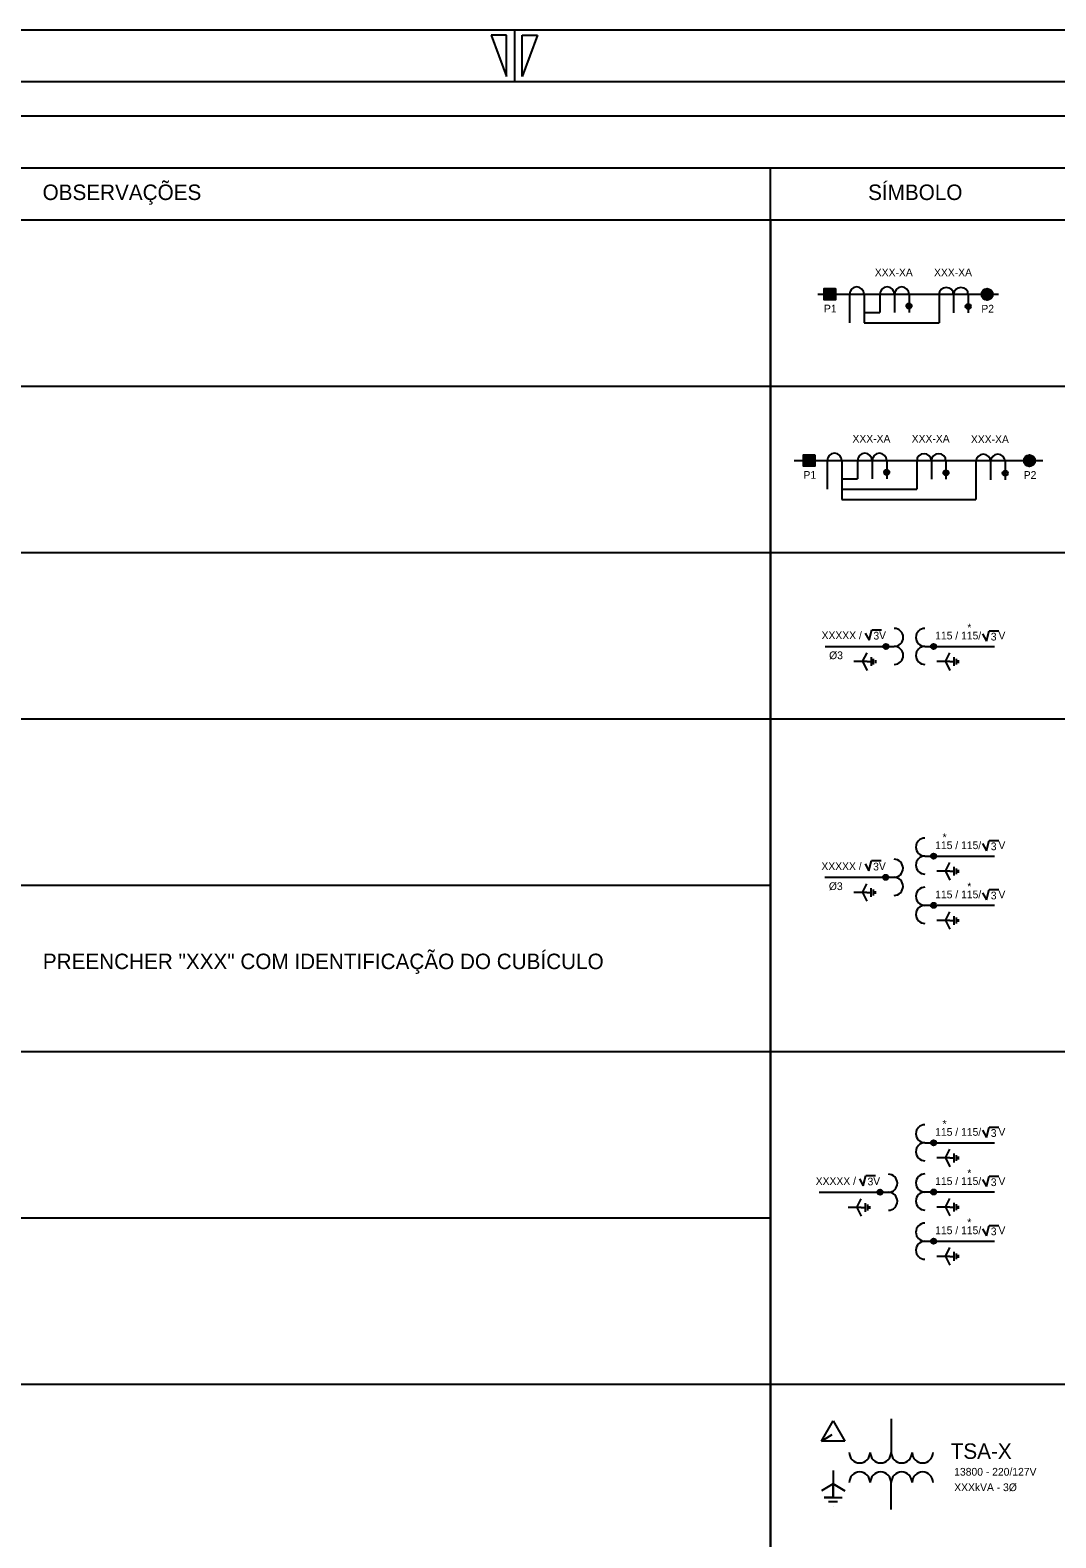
# Model space of a CAD drawing. Extents: x 563 to 3226, y 358 to 960.
# Drawn here: x 1721 to 1919.9, y 659.8 to 952 of the extents above; entities that cross this region are included whole.
import ezdxf

# ---------------------------------------------------------------- set-up
doc = ezdxf.new("R2010")
doc.units = 0
for name, color, linetype in [('COMENTÁRIOS_CEMIG_03-12-2019', 7, 'Continuous'), ('Default', 7, 'Continuous'), ('New Level (0)', 7, 'Continuous')]:
    doc.layers.add(name, color=color, linetype=linetype)

msp = doc.modelspace()

# ---------------------------------------------------------------- linework, layer by layer
at = {"layer": 'COMENTÁRIOS_CEMIG_03-12-2019'}
for p, q in [((1874.91, 901.76), (1877, 899.67)), ((1874.91, 901.58), (1876.82, 899.67)), ((1874.91, 901.41), (1876.64, 899.67)), ((1874.91, 901.23), (1876.47, 899.67)), ((1874.91, 901.05), (1876.29, 899.67)), ((1874.91, 900.88), (1876.11, 899.67)), ((1874.91, 900.7), (1875.94, 899.67)), ((1874.91, 900.52), (1875.76, 899.67)), ((1874.91, 900.35), (1875.58, 899.67)), ((1874.91, 900.17), (1875.41, 899.67)), ((1874.91, 899.99), (1875.23, 899.67)), ((1874.96, 901.88), (1877.12, 899.73)), ((1875.14, 901.88), (1877.12, 899.9)), ((1875.32, 901.88), (1877.12, 900.08)), ((1875.49, 901.88), (1877.12, 900.26)), ((1875.67, 901.88), (1877.12, 900.43)), ((1875.85, 901.88), (1877.12, 900.61)), ((1876.02, 901.88), (1877.12, 900.79)), ((1876.2, 901.88), (1877.12, 900.96)), ((1876.38, 901.88), (1877.12, 901.14)), ((1876.55, 901.88), (1877.12, 901.32)), ((1876.73, 901.88), (1877.12, 901.49)), ((1876.91, 901.88), (1877.12, 901.67)), ((1877.09, 901.88), (1877.12, 901.85)), ((1874.91, 899.82), (1875.05, 899.67)), ((1870.93, 869.53), (1873.02, 867.44)), ((1870.93, 869.36), (1872.85, 867.44)), ((1870.93, 869.18), (1872.67, 867.44)), ((1870.93, 869), (1872.49, 867.44)), ((1870.93, 868.83), (1872.32, 867.44)), ((1870.93, 868.65), (1872.14, 867.44)), ((1870.93, 868.47), (1871.96, 867.44)), ((1870.93, 868.29), (1871.79, 867.44)), ((1870.93, 868.12), (1871.61, 867.44)), ((1870.93, 867.94), (1871.43, 867.44)), ((1870.93, 867.76), (1871.26, 867.44)), ((1870.99, 869.65), (1873.14, 867.5)), ((1871.17, 869.65), (1873.14, 867.67)), ((1871.34, 869.65), (1873.14, 867.85)), ((1871.52, 869.65), (1873.14, 868.03)), ((1871.7, 869.65), (1873.14, 868.2)), ((1871.87, 869.65), (1873.14, 868.38)), ((1872.05, 869.65), (1873.14, 868.56)), ((1872.23, 869.65), (1873.14, 868.74)), ((1872.4, 869.65), (1873.14, 868.91)), ((1872.58, 869.65), (1873.14, 869.09)), ((1872.76, 869.65), (1873.14, 869.27)), ((1872.93, 869.65), (1873.14, 869.44)), ((1873.11, 869.65), (1873.14, 869.62)), ((1870.93, 867.59), (1871.08, 867.44))]:
    msp.add_line(p, q, dxfattribs=at)
for points in [[(1877.12, 901.88), (1877.12, 899.67), (1874.91, 899.67), (1874.91, 901.88)], [(1873.14, 869.65), (1873.14, 867.44), (1870.93, 867.44), (1870.93, 869.65)]]:
    msp.add_lwpolyline(points, close=True, dxfattribs=at)
at = {"layer": 'Default'}
for p, q in [((1873.72, 900.78), (1908.74, 900.78)), ((1879.85, 900.78), (1879.85, 895.24)), ((1879.85, 900.78), (1879.85, 895.24)), ((1882.68, 900.78), (1882.68, 897.24)), ((1882.68, 900.78), (1882.68, 895.24)), ((1885.73, 900.78), (1885.73, 897.24)), ((1885.73, 900.78), (1885.73, 897.24)), ((1888.56, 900.78), (1888.56, 897.24)), ((1888.56, 900.78), (1888.56, 897.24)), ((1891.39, 900.78), (1891.39, 897.24)), ((1891.39, 900.78), (1891.39, 897.24)), ((1897.21, 900.68), (1897.21, 895.24)), ((1900.04, 900.68), (1900.04, 897.15)), ((1902.87, 900.68), (1902.87, 897.15)), ((1905.42, 900.83), (1906.6, 899.65)), ((1905.42, 900.63), (1906.4, 899.66)), ((1905.44, 901), (1906.77, 899.68)), ((1905.48, 900.38), (1906.14, 899.72)), ((1905.49, 901.15), (1906.92, 899.73)), ((1905.55, 901.29), (1907.05, 899.79)), ((1905.63, 901.41), (1907.17, 899.86)), ((1905.71, 901.51), (1907.28, 899.95)), ((1905.82, 901.61), (1907.37, 900.05)), ((1905.93, 901.69), (1907.45, 900.17)), ((1906.06, 901.76), (1907.52, 900.29)), ((1906.2, 901.81), (1907.58, 900.43)), ((1906.36, 901.85), (1907.61, 900.59)), ((1906.54, 901.86), (1907.63, 900.78)), ((1906.76, 901.84), (1907.6, 901)), ((1907.08, 901.71), (1907.47, 901.32)), ((1882.68, 897.24), (1885.73, 897.24)), ((1882.68, 895.24), (1897.21, 895.24)), ((1869.1, 868.55), (1917.35, 868.55)), ((1875.53, 868.55), (1875.53, 863.01)), ((1875.53, 868.55), (1875.53, 863.01)), ((1878.36, 868.55), (1878.36, 865.01)), ((1878.36, 868.55), (1878.36, 861.01)), ((1881.41, 868.55), (1881.41, 865.01)), ((1881.41, 868.55), (1881.41, 865.01)), ((1884.24, 868.55), (1884.24, 865.01)), ((1884.24, 868.55), (1884.24, 865.01)), ((1887.07, 868.55), (1887.07, 865.01)), ((1887.07, 868.55), (1887.07, 865.01)), ((1892.89, 868.46), (1892.89, 863.01)), ((1895.72, 868.46), (1895.72, 864.92)), ((1898.55, 868.46), (1898.55, 864.92)), ((1904.37, 868.36), (1904.37, 861.01)), ((1907.2, 868.36), (1907.2, 864.83)), ((1910.03, 868.36), (1910.03, 864.83)), ((1913.63, 868.61), (1914.81, 867.43)), ((1913.64, 868.41), (1914.61, 867.43)), ((1913.66, 868.78), (1914.98, 867.45)), ((1913.7, 868.93), (1915.13, 867.5)), ((1913.7, 868.15), (1914.36, 867.49)), ((1913.76, 869.06), (1915.27, 867.56)), ((1913.84, 869.18), (1915.38, 867.63)), ((1913.93, 869.29), (1915.49, 867.72)), ((1914.03, 869.38), (1915.59, 867.82)), ((1914.14, 869.46), (1915.67, 867.94)), ((1914.27, 869.53), (1915.74, 868.06)), ((1914.41, 869.59), (1915.79, 868.2)), ((1914.57, 869.62), (1915.83, 868.36)), ((1914.75, 869.63), (1915.84, 868.55)), ((1914.97, 869.61), (1915.81, 868.77)), ((1915.3, 869.48), (1915.69, 869.09)), ((1878.36, 865.01), (1881.41, 865.01)), ((1878.36, 863.01), (1892.89, 863.01)), ((1878.36, 861.01), (1904.37, 861.01)), ((1883.66, 833.77), (1884.16, 835.77)), ((1884.16, 835.77), (1886.04, 835.77)), ((1906.41, 833.58), (1906.91, 835.59)), ((1906.91, 835.59), (1908.79, 835.59)), ((1882.9, 835.14), (1883.66, 833.77)), ((1905.65, 834.96), (1906.41, 833.58)), ((1875.11, 832.54), (1888.52, 832.54)), ((1882.4, 829.6), (1883.25, 831.3)), ((1884.1, 829.6), (1884.1, 830.45)), ((1884.52, 829.6), (1884.52, 830.16)), ((1884.95, 829.6), (1884.95, 829.88)), ((1894.48, 832.54), (1907.98, 832.54)), ((1898.46, 829.6), (1899.31, 831.3)), ((1900.16, 829.6), (1900.16, 830.45)), ((1900.58, 829.6), (1900.58, 830.16)), ((1901.01, 829.6), (1901.01, 829.88)), ((1882.4, 829.6), (1880.7, 829.6)), ((1883.25, 829.6), (1882.4, 829.6)), ((1882.4, 829.6), (1883.25, 827.9)), ((1883.25, 829.6), (1884.1, 829.6)), ((1884.1, 828.75), (1884.1, 829.6)), ((1884.52, 829.03), (1884.52, 829.6)), ((1884.95, 829.31), (1884.95, 829.6)), ((1898.46, 829.6), (1896.76, 829.6)), ((1899.31, 829.6), (1898.46, 829.6)), ((1898.46, 829.6), (1899.31, 827.9)), ((1899.31, 829.6), (1900.16, 829.6)), ((1900.16, 828.75), (1900.16, 829.6)), ((1900.58, 829.03), (1900.58, 829.6)), ((1901.01, 829.31), (1901.01, 829.6)), ((1906.41, 792.95), (1906.91, 794.95)), ((1906.91, 794.95), (1908.79, 794.95)), ((1894.48, 791.91), (1907.98, 791.91)), ((1905.65, 794.33), (1906.41, 792.95)), ((1882.86, 790.4), (1883.61, 789.03)), ((1883.61, 789.03), (1884.11, 791.03)), ((1884.11, 791.03), (1886, 791.03)), ((1898.46, 788.97), (1896.76, 788.97)), ((1898.46, 788.97), (1899.31, 790.67)), ((1899.31, 788.97), (1898.46, 788.97)), ((1898.46, 788.97), (1899.31, 787.27)), ((1899.31, 788.97), (1900.16, 788.97)), ((1900.16, 788.97), (1900.16, 789.82)), ((1900.16, 788.12), (1900.16, 788.97)), ((1900.58, 788.97), (1900.58, 789.53)), ((1900.58, 788.4), (1900.58, 788.97)), ((1901.01, 788.97), (1901.01, 789.25)), ((1901.01, 788.68), (1901.01, 788.97)), ((1875.07, 787.8), (1888.48, 787.8)), ((1882.35, 784.86), (1883.2, 786.55)), ((1882.35, 784.86), (1880.66, 784.86)), ((1883.2, 784.86), (1882.35, 784.86)), ((1882.35, 784.86), (1883.2, 783.16)), ((1883.2, 784.86), (1884.05, 784.86)), ((1884.05, 784.86), (1884.05, 785.71)), ((1884.05, 784.01), (1884.05, 784.86)), ((1884.48, 784.86), (1884.48, 785.42)), ((1884.48, 784.29), (1884.48, 784.86)), ((1884.9, 784.86), (1884.9, 785.14)), ((1884.9, 784.57), (1884.9, 784.86)), ((1905.65, 784.79), (1906.41, 783.42)), ((1906.41, 783.42), (1906.91, 785.42)), ((1906.91, 785.42), (1908.79, 785.42)), ((1907.98, 782.33), (1894.07, 782.33)), ((1898.46, 779.43), (1899.31, 781.13)), ((1900.16, 779.43), (1900.16, 780.28)), ((1898.46, 779.43), (1896.76, 779.43)), ((1899.31, 779.43), (1898.46, 779.43)), ((1898.46, 779.43), (1899.31, 777.74)), ((1899.31, 779.43), (1900.16, 779.43)), ((1900.16, 778.59), (1900.16, 779.43)), ((1900.58, 779.43), (1900.58, 779.99)), ((1900.58, 778.87), (1900.58, 779.43)), ((1901.01, 779.43), (1901.01, 779.71)), ((1901.01, 779.15), (1901.01, 779.43)), ((1906.41, 737.4), (1906.91, 739.4)), ((1906.91, 739.4), (1908.79, 739.4)), ((1894.48, 736.36), (1907.98, 736.36)), ((1905.65, 738.78), (1906.41, 737.4)), ((1898.46, 733.42), (1896.76, 733.42)), ((1898.46, 733.42), (1899.31, 735.11)), ((1899.31, 733.42), (1898.46, 733.42)), ((1898.46, 733.42), (1899.31, 731.72)), ((1899.31, 733.42), (1900.16, 733.42)), ((1900.16, 733.42), (1900.16, 734.27)), ((1900.16, 732.57), (1900.16, 733.42)), ((1900.58, 733.42), (1900.58, 733.98)), ((1900.58, 732.85), (1900.58, 733.42)), ((1901.01, 733.42), (1901.01, 733.7)), ((1901.01, 733.13), (1901.01, 733.42)), ((1881.76, 729.38), (1882.52, 728)), ((1882.52, 728), (1883.02, 730.01)), ((1883.02, 730.01), (1884.9, 730.01)), ((1905.65, 729.24), (1906.41, 727.87)), ((1906.41, 727.87), (1906.91, 729.87)), ((1906.91, 729.87), (1908.79, 729.87)), ((1873.97, 726.78), (1887.38, 726.78)), ((1881.26, 723.83), (1882.11, 725.53)), ((1882.96, 723.83), (1882.96, 724.68)), ((1907.98, 726.78), (1894.07, 726.78)), ((1898.46, 723.88), (1899.31, 725.58)), ((1900.16, 723.88), (1900.16, 724.73)), ((1881.26, 723.83), (1879.56, 723.83)), ((1882.11, 723.83), (1881.26, 723.83)), ((1881.26, 723.83), (1882.11, 722.14)), ((1882.11, 723.83), (1882.96, 723.83)), ((1882.96, 722.99), (1882.96, 723.83)), ((1883.38, 723.83), (1883.38, 724.39)), ((1883.38, 723.27), (1883.38, 723.83)), ((1883.81, 723.83), (1883.81, 724.11)), ((1883.81, 723.55), (1883.81, 723.83)), ((1898.46, 723.88), (1896.76, 723.88)), ((1899.31, 723.88), (1898.46, 723.88)), ((1898.46, 723.88), (1899.31, 722.18)), ((1899.31, 723.88), (1900.16, 723.88)), ((1900.16, 723.03), (1900.16, 723.88)), ((1900.58, 723.88), (1900.58, 724.44)), ((1900.58, 723.31), (1900.58, 723.88)), ((1901.01, 723.88), (1901.01, 724.16)), ((1901.01, 723.59), (1901.01, 723.88)), ((1905.65, 719.71), (1906.41, 718.33)), ((1906.41, 718.33), (1906.91, 720.34)), ((1906.91, 720.34), (1908.79, 720.34)), ((1907.98, 717.24), (1894.07, 717.24)), ((1898.46, 714.35), (1899.31, 716.05)), ((1898.46, 714.35), (1896.76, 714.35)), ((1899.31, 714.35), (1898.46, 714.35)), ((1898.46, 714.35), (1899.31, 712.65)), ((1899.31, 714.35), (1900.16, 714.35)), ((1900.16, 714.35), (1900.16, 715.2)), ((1900.16, 713.5), (1900.16, 714.35)), ((1900.58, 714.35), (1900.58, 714.91)), ((1900.58, 713.78), (1900.58, 714.35)), ((1901.01, 714.35), (1901.01, 714.63)), ((1901.01, 714.06), (1901.01, 714.35)), ((1874.41, 678.55), (1876.67, 682.47)), ((1874.41, 678.55), (1876.67, 682.47)), ((1874.41, 678.55), (1876.67, 682.47)), ((1874.41, 678.55), (1876.67, 682.47)), ((1874.41, 678.55), (1876.67, 682.47)), ((1876.67, 682.47), (1878.93, 678.55)), ((1876.67, 682.47), (1878.93, 678.55)), ((1876.67, 682.47), (1878.93, 678.55)), ((1876.67, 682.47), (1878.93, 678.55)), ((1876.67, 682.47), (1878.93, 678.55)), ((1887.92, 682.86), (1887.92, 676.35)), ((1874.41, 678.55), (1876.51, 679.83)), ((1878.93, 678.55), (1874.41, 678.55)), ((1878.93, 678.55), (1874.41, 678.55)), ((1878.93, 678.55), (1874.41, 678.55)), ((1878.93, 678.55), (1874.41, 678.55)), ((1878.93, 678.55), (1874.41, 678.55)), ((1876.66, 672.86), (1876.66, 667.64)), ((1876.66, 672.86), (1876.66, 667.64)), ((1876.66, 672.86), (1876.66, 667.64)), ((1876.66, 672.86), (1876.66, 667.64)), ((1876.66, 672.86), (1876.66, 667.64)), ((1876.66, 670.25), (1874.4, 668.94)), ((1876.66, 670.25), (1874.4, 668.94)), ((1876.66, 670.25), (1874.4, 668.94)), ((1876.66, 670.25), (1874.4, 668.94)), ((1876.66, 670.25), (1874.4, 668.94)), ((1876.66, 670.25), (1878.93, 668.94)), ((1876.66, 670.25), (1878.93, 668.94)), ((1878.93, 668.94), (1876.66, 670.25)), ((1876.66, 670.25), (1878.93, 668.94)), ((1878.93, 668.94), (1876.66, 670.25)), ((1876.66, 670.25), (1878.93, 668.94)), ((1878.93, 668.94), (1876.66, 670.25)), ((1876.66, 667.64), (1876.66, 670.25)), ((1876.66, 670.25), (1878.93, 668.94)), ((1878.93, 668.94), (1876.66, 670.25)), ((1887.92, 665.3), (1887.92, 670.54)), ((1874.92, 667.64), (1878.41, 667.64)), ((1876.66, 667.64), (1874.92, 667.64)), ((1874.92, 667.64), (1878.41, 667.64)), ((1876.66, 667.64), (1874.92, 667.64)), ((1874.92, 667.64), (1878.41, 667.64)), ((1876.66, 667.64), (1874.92, 667.64)), ((1874.92, 667.64), (1878.41, 667.64)), ((1876.66, 667.64), (1874.92, 667.64)), ((1877.54, 666.76), (1875.79, 666.76)), ((1877.54, 666.76), (1875.79, 666.76)), ((1877.54, 666.76), (1875.79, 666.76)), ((1877.54, 666.76), (1875.79, 666.76)), ((1877.54, 666.76), (1875.79, 666.76)), ((1876.66, 665.89), (1876.66, 665.89)), ((1876.66, 665.89), (1876.66, 665.89)), ((1876.66, 665.89), (1876.66, 665.89)), ((1876.66, 665.89), (1876.66, 665.89)), ((1876.66, 665.89), (1876.66, 665.89))]:
    msp.add_line(p, q, dxfattribs=at)
for centre, radius in [((1906.52, 900.76), 1.11), ((1891.39, 898.51), 0.501), ((1891.39, 898.51), 0.282), ((1902.87, 898.41), 0.501), ((1902.87, 898.41), 0.282), ((1914.73, 868.53), 1.11), ((1887.07, 866.28), 0.501), ((1887.07, 866.28), 0.282), ((1898.55, 866.19), 0.501), ((1898.55, 866.19), 0.282), ((1910.03, 866.09), 0.501), ((1910.03, 866.09), 0.282), ((1886.91, 832.54), 0.501), ((1886.91, 832.54), 0.282), ((1896.15, 832.54), 0.501), ((1896.15, 832.54), 0.282), ((1896.15, 791.91), 0.501), ((1896.15, 791.91), 0.282), ((1886.86, 787.8), 0.501), ((1886.86, 787.8), 0.282), ((1896.15, 782.37), 0.501), ((1896.15, 782.37), 0.282), ((1896.15, 736.36), 0.501), ((1896.15, 736.36), 0.282), ((1885.77, 726.78), 0.501), ((1885.77, 726.78), 0.282), ((1896.15, 726.82), 0.501), ((1896.15, 726.82), 0.282), ((1896.15, 717.29), 0.501), ((1896.15, 717.29), 0.282)]:
    msp.add_circle(centre, radius, dxfattribs=at)
for centre, radius, start, end in [((1881.26, 900.78), 1.42, 0, 180), ((1881.26, 900.78), 1.42, 0, 180), ((1887.15, 900.78), 1.42, 0, 180), ((1887.15, 900.78), 1.42, 0, 180), ((1889.98, 900.78), 1.42, 0, 180), ((1889.98, 900.78), 1.42, 0, 180), ((1898.62, 900.68), 1.42, 0, 180), ((1901.45, 900.68), 1.42, 0, 180), ((1876.94, 868.55), 1.42, 0, 180), ((1876.94, 868.55), 1.42, 0, 180), ((1882.82, 868.55), 1.42, 0, 180), ((1882.82, 868.55), 1.42, 0, 180), ((1885.65, 868.55), 1.42, 0, 180), ((1885.65, 868.55), 1.42, 0, 180), ((1894.3, 868.46), 1.42, 0, 180), ((1897.13, 868.46), 1.42, 0, 180), ((1905.78, 868.36), 1.42, 0, 180), ((1908.61, 868.36), 1.42, 0, 180), ((1888.52, 834.29), 1.75, 270, 90), ((1894.48, 834.29), 1.75, 90, 270), ((1888.52, 830.79), 1.75, 270, 90), ((1894.48, 830.79), 1.75, 90, 270), ((1894.48, 793.66), 1.75, 90, 270), ((1894.48, 790.16), 1.75, 90, 270), ((1888.48, 789.55), 1.75, 270, 90), ((1888.48, 786.05), 1.75, 270, 90), ((1894.48, 784.12), 1.75, 90, 270), ((1894.48, 780.62), 1.75, 90, 270), ((1894.48, 738.11), 1.75, 90, 270), ((1894.48, 734.61), 1.75, 90, 270), ((1887.38, 728.53), 1.75, 270, 90), ((1894.48, 728.57), 1.75, 90, 270), ((1887.38, 725.03), 1.75, 270, 90), ((1894.48, 725.07), 1.75, 90, 270), ((1894.48, 719.04), 1.75, 90, 270), ((1894.48, 715.54), 1.75, 90, 270), ((1881.82, 676.35), 2.03, 180, 0), ((1881.82, 676.35), 2.03, 180, 0), ((1881.82, 676.35), 2.03, 180, 0), ((1881.82, 676.35), 2.03, 180, 0), ((1881.82, 676.35), 2.03, 180, 0), ((1881.82, 676.35), 2.03, 180, 0), ((1881.82, 676.35), 2.03, 180, 0), ((1885.89, 676.35), 2.03, 180, 0), ((1885.89, 676.35), 2.03, 180, 0), ((1885.89, 676.35), 2.03, 180, 0), ((1885.89, 676.35), 2.03, 180, 0), ((1889.96, 676.35), 2.03, 180, 0), ((1889.96, 676.35), 2.03, 180, 0), ((1889.96, 676.35), 2.03, 180, 0), ((1889.96, 676.35), 2.03, 180, 0), ((1889.96, 676.35), 2.03, 180, 0), ((1889.96, 676.35), 2.03, 180, 0), ((1889.96, 676.35), 2.03, 180, 0), ((1889.96, 676.35), 2.03, 180, 0), ((1889.96, 676.35), 2.03, 180, 0), ((1889.96, 676.35), 2.03, 180, 0), ((1889.96, 676.35), 2.03, 180, 0), ((1894.02, 676.35), 2.03, 180, 0), ((1881.82, 670.54), 2.03, 0, 180), ((1881.82, 670.54), 2.03, 0, 180), ((1881.82, 670.54), 2.03, 0, 180), ((1881.82, 670.54), 2.03, 0, 180), ((1881.82, 670.54), 2.03, 0, 180), ((1881.82, 670.54), 2.03, 0, 180), ((1881.82, 670.54), 2.03, 0, 180), ((1881.82, 670.54), 2.03, 0, 180), ((1881.82, 670.54), 2.03, 0, 180), ((1885.89, 670.54), 2.03, 0, 180), ((1885.89, 670.54), 2.03, 0, 180), ((1885.89, 670.54), 2.03, 0, 180), ((1885.89, 670.54), 2.03, 0, 180), ((1885.89, 670.54), 2.03, 0, 180), ((1885.89, 670.54), 2.03, 0, 180), ((1885.89, 670.54), 2.03, 0, 180), ((1885.89, 670.54), 2.03, 0, 180), ((1885.89, 670.54), 2.03, 0, 180), ((1889.96, 670.54), 2.03, 0, 180), ((1889.96, 670.54), 2.03, 0, 180), ((1889.96, 670.54), 2.03, 0, 180), ((1889.96, 670.54), 2.03, 0, 180), ((1889.96, 670.54), 2.03, 0, 180), ((1889.96, 670.54), 2.03, 0, 180), ((1889.96, 670.54), 2.03, 0, 180), ((1889.96, 670.54), 2.03, 0, 180), ((1889.96, 670.54), 2.03, 0, 180), ((1889.96, 670.54), 2.03, 0, 180), ((1889.96, 670.54), 2.03, 0, 180), ((1889.96, 670.54), 2.03, 0, 180), ((1889.96, 670.54), 2.03, 0, 180), ((1894.02, 670.54), 2.03, 0, 180)]:
    msp.add_arc(centre, radius, start, end, dxfattribs=at)
at = {"layer": 'New Level (0)'}
for p, q in [((2314.88, 951.96), (1473.88, 951.96)), ((2314.88, 951.96), (1473.88, 951.96)), ((1813.38, 950.96), (1810.38, 950.96)), ((1810.38, 950.96), (1813.38, 942.96)), ((1813.38, 942.96), (1813.38, 950.96)), ((1814.88, 951.96), (1814.88, 941.96)), ((1816.38, 942.96), (1816.38, 950.96)), ((1816.38, 950.96), (1819.38, 950.96)), ((1819.38, 950.96), (1816.38, 942.96)), ((2304.88, 941.96), (1483.88, 941.96)), ((1514.44, 935.35), (2214.61, 935.35)), ((1514.44, 925.28), (1886.12, 925.28)), ((1864.53, 915.21), (1864.53, 925.28)), ((1864.53, 923.47), (1864.53, 925.28)), ((1864.53, 925.28), (2214.61, 925.28)), ((1864.53, 915.21), (1864.53, 923.47)), ((1514.44, 882.98), (2214.61, 882.98)), ((1514.44, 850.75), (2214.61, 850.75)), ((1514.44, 818.53), (2214.61, 818.53)), ((1514.44, 786.3), (1864.53, 786.3)), ((1514.44, 754.07), (2214.61, 754.07)), ((1514.44, 721.84), (1864.53, 721.84)), ((1514.44, 689.61), (2214.61, 689.61))]:
    msp.add_line(p, q, dxfattribs=at)
for points in [[(1718.4, 915.21), (1864.53, 915.21), (1864.53, 429.83), (1718.4, 429.83)], [(1864.53, 915.21), (2068.49, 915.21), (2068.49, 429.83), (1864.53, 429.83)]]:
    msp.add_lwpolyline(points, close=True, dxfattribs=at)

# ---------------------------------------------------------------- texts
at = {"layer": 'Default'}
for s, height, p in [('OBSERVAÇÕES', 3, (1723.42, 919.04)), ('SÍMBOLO', 3, (1883.46, 919.04)), ('XXX-XA', 1.5, (1884.76, 904.26)), ('XXX-XA', 1.5, (1896.24, 904.26)), ('P1', 1.5, (1874.9, 897.25)), ('P2', 1.5, (1905.41, 897.23)), ('XXX-XA', 1.5, (1880.43, 872.04)), ('XXX-XA', 1.5, (1891.91, 872.04)), ('XXX-XA', 1.5, (1903.39, 871.94)), ('P1', 1.5, (1870.93, 865.02)), ('P2', 1.5, (1913.63, 865.01)), ('*', 1.5, (1902.69, 835.46)), ('XXXXX /      V', 1.5, (1874.44, 833.95)), ('3', 1.5, (1884.49, 833.87)), ('115 / 115/      V', 1.5, (1896.46, 833.9)), ('3', 1.5, (1907.24, 833.69)), ('Ø3', 1.5, (1875.9, 830.07)), ('115 / 115/      V', 1.5, (1896.46, 793.27)), ('*', 1.5, (1897.89, 794.82)), ('3', 1.5, (1907.24, 793.05)), ('XXXXX /      V', 1.5, (1874.4, 789.21)), ('3', 1.5, (1884.44, 789.13)), ('Ø3', 1.5, (1875.85, 785.33)), ('*', 1.5, (1902.69, 785.29)), ('115 / 115/      V', 1.5, (1896.46, 783.73)), ('3', 1.5, (1907.24, 783.52)), ('PREENCHER "XXX" COM IDENTIFICAÇÃO DO CUBÍCULO', 3, (1723.47, 770.01)), ('115 / 115/      V', 1.5, (1896.46, 737.72)), ('*', 1.5, (1897.89, 739.27)), ('3', 1.5, (1907.24, 737.5)), ('*', 1.5, (1902.69, 729.74)), ('XXXXX /      V', 1.5, (1873.3, 728.19)), ('3', 1.5, (1883.35, 728.11)), ('115 / 115/      V', 1.5, (1896.46, 728.18)), ('3', 1.5, (1907.24, 727.97)), ('*', 1.5, (1902.69, 720.21)), ('115 / 115/      V', 1.5, (1896.46, 718.65)), ('3', 1.5, (1907.24, 718.44)), ('TSA-X', 3, (1899.47, 675.11)), ('13800 - 220/127V', 1.5, (1900.15, 671.86)), ('XXXkVA - 3Ø', 1.5, (1900.15, 668.86))]:
    msp.add_text(s, height=height, dxfattribs=at).set_placement(p)

doc.saveas('drawing.dxf')
